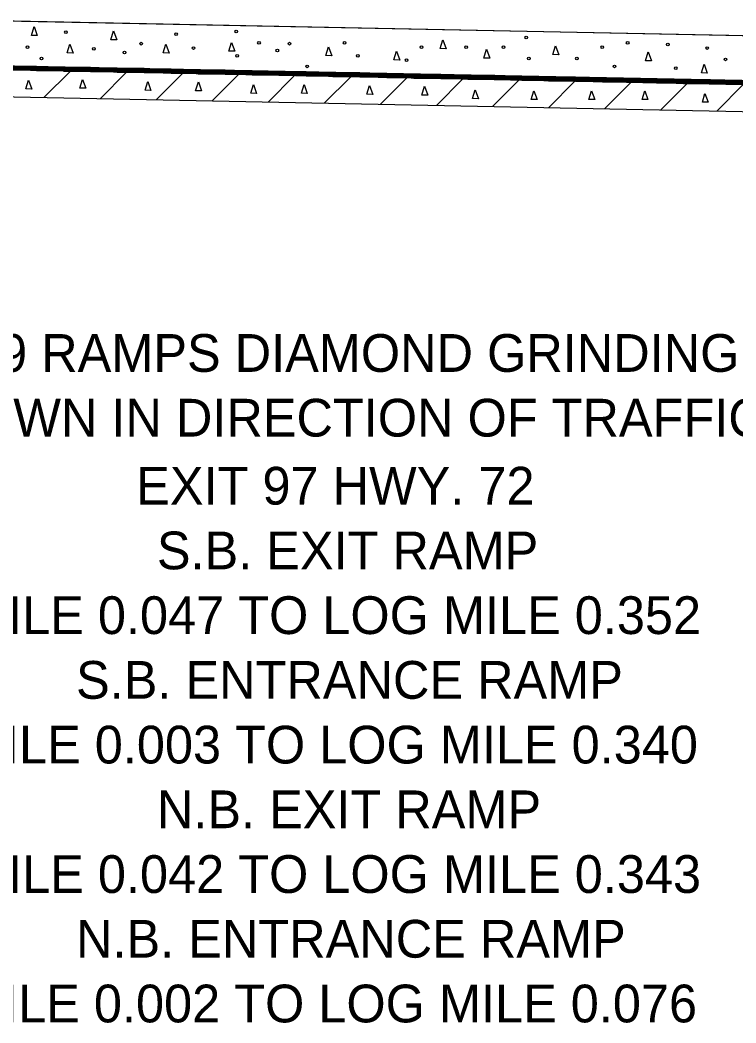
# Model space of a CAD drawing. Extents: x 60325 to 61047, y 53669 to 53767.
# Drawn here: x 60760.99 to 60774.27, y 53721.62 to 53740.21 of the extents above; entities that cross this region are included whole.
import ezdxf

# ---------------------------------------------------------------- set-up
doc = ezdxf.new("R2010")
doc.units = 0
doc.layers.add('R_Border', color=7, linetype='Continuous')
doc.layers.add('R_Border Prem', color=7, linetype='Continuous')

msp = doc.modelspace()

# ---------------------------------------------------------------- linework, layer by layer
at = {"layer": 'R_Border'}
msp.add_lwpolyline([(60760.077, 53740.212), (60775.077, 53739.912)], dxfattribs=at)
at = {"layer": 'R_Border Prem'}
for p, q in [((60760.077, 53740.212), (60775.077, 53739.912)), ((60758.077, 53739.337), (60762.298, 53739.337)), ((60758.077, 53739.327), (60762.798, 53739.327)), ((60758.077, 53739.317), (60763.298, 53739.317)), ((60758.077, 53739.307), (60763.798, 53739.307)), ((60758.356, 53739.347), (60761.798, 53739.347)), ((60758.856, 53739.357), (60761.298, 53739.357)), ((60760.077, 53739.382), (60777.077, 53739.042)), ((60760.077, 53739.302), (60777.077, 53738.962)), ((60760.298, 53739.297), (60764.298, 53739.297)), ((60760.798, 53739.287), (60764.798, 53739.287)), ((60761.298, 53739.277), (60765.298, 53739.277)), ((60761.437, 53738.774), (60761.928, 53739.265)), ((60761.798, 53739.267), (60765.798, 53739.267)), ((60762.298, 53739.257), (60766.298, 53739.257)), ((60762.477, 53738.754), (60762.968, 53739.244)), ((60762.798, 53739.247), (60766.798, 53739.247)), ((60763.298, 53739.237), (60767.298, 53739.237)), ((60763.517, 53738.733), (60764.007, 53739.223)), ((60763.798, 53739.227), (60767.798, 53739.227)), ((60764.298, 53739.217), (60768.298, 53739.217)), ((60764.557, 53738.712), (60765.047, 53739.202)), ((60764.798, 53739.207), (60768.798, 53739.207)), ((60765.298, 53739.197), (60769.298, 53739.197)), ((60765.597, 53738.691), (60766.087, 53739.181)), ((60765.798, 53739.187), (60769.798, 53739.187)), ((60766.298, 53739.177), (60770.298, 53739.177)), ((60766.637, 53738.67), (60767.127, 53739.161)), ((60766.798, 53739.167), (60770.798, 53739.167)), ((60767.298, 53739.157), (60771.298, 53739.157)), ((60767.677, 53738.65), (60768.167, 53739.14)), ((60767.798, 53739.147), (60771.798, 53739.147)), ((60768.298, 53739.137), (60772.298, 53739.137)), ((60768.717, 53738.629), (60769.207, 53739.119)), ((60768.798, 53739.127), (60772.798, 53739.127)), ((60769.298, 53739.117), (60773.298, 53739.117)), ((60769.756, 53738.608), (60770.247, 53739.098)), ((60769.798, 53739.107), (60773.798, 53739.107)), ((60770.298, 53739.097), (60774.298, 53739.097)), ((60770.796, 53738.587), (60771.286, 53739.077)), ((60770.798, 53739.087), (60774.798, 53739.087)), ((60771.298, 53739.077), (60775.298, 53739.077)), ((60771.798, 53739.067), (60775.798, 53739.067)), ((60771.836, 53738.566), (60772.326, 53739.057)), ((60772.298, 53739.057), (60776.298, 53739.057)), ((60772.798, 53739.047), (60776.798, 53739.047)), ((60772.876, 53738.546), (60773.366, 53739.036)), ((60773.298, 53739.037), (60777.077, 53739.037)), ((60773.798, 53739.027), (60777.077, 53739.027)), ((60773.916, 53738.525), (60774.406, 53739.015)), ((60760.077, 53738.802), (60789.872, 53738.206))]:
    msp.add_line(p, q, dxfattribs=at)
for points in [[(60761.254, 53740.09), (60761.314, 53739.924), (60761.204, 53739.928), (60761.254, 53740.09)], [(60762.728, 53740.009), (60762.789, 53739.843), (60762.679, 53739.847), (60762.728, 53740.009)], [(60768.836, 53739.847), (60768.896, 53739.681), (60768.786, 53739.685), (60768.836, 53739.847)], [(60761.918, 53739.766), (60761.979, 53739.6), (60761.869, 53739.604), (60761.918, 53739.766)], [(60763.7, 53739.766), (60763.761, 53739.6), (60763.651, 53739.604), (60763.7, 53739.766)], [(60764.915, 53739.798), (60764.976, 53739.632), (60764.866, 53739.637), (60764.915, 53739.798)], [(60766.713, 53739.717), (60766.774, 53739.551), (60766.664, 53739.556), (60766.713, 53739.717)], [(60767.977, 53739.636), (60768.038, 53739.47), (60767.928, 53739.475), (60767.977, 53739.636)], [(60769.646, 53739.669), (60769.706, 53739.503), (60769.596, 53739.507), (60769.646, 53739.669)], [(60770.926, 53739.733), (60770.986, 53739.567), (60770.876, 53739.572), (60770.926, 53739.733)], [(60772.643, 53739.62), (60772.703, 53739.454), (60772.593, 53739.458), (60772.643, 53739.62)], [(60773.68, 53739.393), (60773.74, 53739.227), (60773.63, 53739.232), (60773.68, 53739.393)], [(60761.15, 53739.096), (60761.211, 53738.93), (60761.101, 53738.935), (60761.15, 53739.096)], [(60762.154, 53739.112), (60762.215, 53738.946), (60762.105, 53738.951), (60762.154, 53739.112)], [(60763.361, 53739.072), (60763.422, 53738.906), (60763.312, 53738.91), (60763.361, 53739.072)], [(60764.301, 53739.064), (60764.361, 53738.898), (60764.251, 53738.902), (60764.301, 53739.064)], [(60765.322, 53739.015), (60765.382, 53738.849), (60765.272, 53738.854), (60765.322, 53739.015)], [(60766.261, 53739.015), (60766.322, 53738.849), (60766.212, 53738.854), (60766.261, 53739.015)], [(60767.476, 53738.999), (60767.537, 53738.833), (60767.427, 53738.838), (60767.476, 53738.999)], [(60768.497, 53738.983), (60768.557, 53738.817), (60768.447, 53738.821), (60768.497, 53738.983)], [(60769.437, 53738.918), (60769.497, 53738.752), (60769.387, 53738.757), (60769.437, 53738.918)], [(60770.522, 53738.902), (60770.582, 53738.736), (60770.472, 53738.74), (60770.522, 53738.902)], [(60771.591, 53738.902), (60771.652, 53738.736), (60771.542, 53738.74), (60771.591, 53738.902)], [(60772.579, 53738.902), (60772.64, 53738.736), (60772.53, 53738.74), (60772.579, 53738.902)], [(60773.697, 53738.853), (60773.758, 53738.687), (60773.648, 53738.692), (60773.697, 53738.853)]]:
    msp.add_lwpolyline(points, dxfattribs=at)
for centre in [(60761.846, 53739.985), (60765.005, 53740.001), (60763.887, 53739.952), (60765.426, 53739.79), (60767.014, 53739.79), (60770.383, 53739.888), (60772.263, 53739.79), (60761.133, 53739.709), (60762.364, 53739.677), (60762.931, 53739.612), (60763.239, 53739.774), (60764.211, 53739.693), (60765.766, 53739.645), (60765.993, 53739.774), (60768.439, 53739.709), (60769.266, 53739.709), (60769.962, 53739.709), (60771.793, 53739.709), (60773.008, 53739.758), (60773.737, 53739.693), (60761.392, 53739.499), (60765.021, 53739.547), (60767.257, 53739.547), (60768.164, 53739.466), (60770.432, 53739.499), (60771.323, 53739.499), (60774.077, 53739.483), (60766.317, 53739.353), (60772.02, 53739.353), (60773.154, 53739.321)]:
    msp.add_circle(centre, 0.025, dxfattribs=at)

# ---------------------------------------------------------------- texts
at = {"layer": 'R_Border'}
for s, p in [('I-49 RAMPS DIAMOND GRINDING', (60759.513, 53733.689)), ('(SHOWN IN DIRECTION OF TRAFFIC)', (60758.529, 53732.489)), ('EXIT 97 HWY. 72', (60763.149, 53731.228)), ('S.B. EXIT RAMP', (60763.532, 53730.028)), ('LOG MILE 0.047 TO LOG MILE 0.352', (60757.756, 53728.828)), ('S.B. ENTRANCE RAMP', (60762.033, 53727.628)), ('LOG MILE 0.003 TO LOG MILE 0.340', (60757.698, 53726.428)), ('N.B. EXIT RAMP', (60763.532, 53725.228)), ('LOG MILE 0.042 TO LOG MILE 0.343', (60757.756, 53724.028)), ('N.B. ENTRANCE RAMP', (60762.033, 53722.828)), ('LOG MILE 0.002 TO LOG MILE 0.076', (60757.682, 53721.628))]:
    msp.add_text(s, height=0.7, dxfattribs=at).set_placement(p)

doc.saveas('drawing.dxf')
